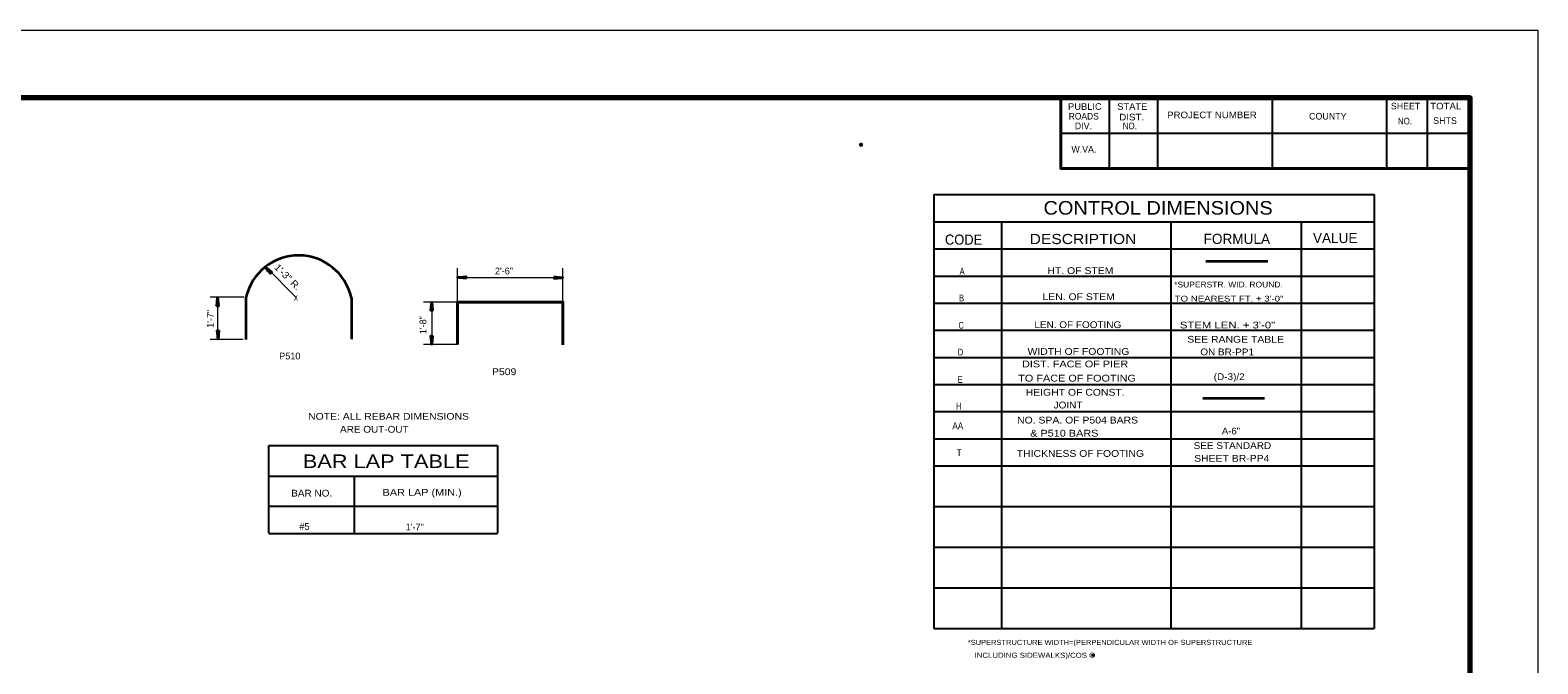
# Model space of a CAD drawing. Extents: x 3.64 to 6.84, y -0.8 to 1.19.
# Drawn here: x 4.986 to 6.841, y 0.413 to 1.192 of the extents above; entities that cross this region are included whole.
import ezdxf
from ezdxf.enums import TextEntityAlignment as Align

# ---------------------------------------------------------------- set-up
doc = ezdxf.new("R2010")
doc.units = 0
doc.header["$LTSCALE"] = 0.0033
doc.header["$PDMODE"] = 32
doc.header["$PDSIZE"] = 0.00165
doc.layers.add('1', color=7, linetype='Continuous', lineweight=40)

msp = doc.modelspace()

# ---------------------------------------------------------------- linework, layer by layer
at = {"layer": '1', "lineweight": 13}
for p, q in [((3.644833, 1.192083), (6.84125, 1.192083)), ((6.8415, 1.191917), (6.8415, -0.7945)), ((5.313417, 0.86375), (5.276333, 0.900833)), ((5.512167, 0.85775), (5.512167, 0.899417)), ((5.641833, 0.85775), (5.641833, 0.899417)), ((5.512667, 0.887833), (5.64025, 0.887833)), ((5.249333, 0.86375), (5.207667, 0.86375)), ((5.217083, 0.864083), (5.217083, 0.812583)), ((5.512167, 0.85775), (5.4705, 0.85775)), ((5.480417, 0.85775), (5.480417, 0.80625)), ((5.248333, 0.81175), (5.208, 0.81175)), ((5.512167, 0.8055), (5.4705, 0.8055))]:
    msp.add_line(p, q, dxfattribs=at)
at = {"layer": '1', "lineweight": 25}
for p, q in [((6.314083, 1.10875), (6.314083, 1.022083)), ((6.373667, 1.10875), (6.373667, 1.022083)), ((6.5145, 1.10875), (6.5145, 1.022083)), ((6.655333, 1.10875), (6.655333, 1.022083)), ((6.705167, 1.10875), (6.705167, 1.022083)), ((6.2545, 1.065417), (6.75825, 1.065417)), ((6.098417, 0.989833), (6.098417, 0.456333)), ((6.098417, 0.989833), (6.640083, 0.989833)), ((6.640083, 0.989833), (6.640083, 0.456333)), ((6.098417, 0.956333), (6.640083, 0.956333)), ((6.18175, 0.956333), (6.18175, 0.456333)), ((6.390083, 0.956333), (6.390083, 0.456333)), ((6.550417, 0.956333), (6.550417, 0.456333)), ((6.098417, 0.923), (6.640083, 0.923)), ((6.098417, 0.889667), (6.640083, 0.889667)), ((6.098417, 0.856333), (6.640083, 0.856333)), ((6.098417, 0.823), (6.640083, 0.823)), ((6.098417, 0.789667), (6.640083, 0.789667)), ((6.098417, 0.756333), (6.640083, 0.756333)), ((6.098417, 0.723), (6.640083, 0.723)), ((6.098417, 0.689667), (6.640083, 0.689667)), ((5.28, 0.68125), (5.561417, 0.68125)), ((5.28, 0.573417), (5.28, 0.68125)), ((5.561417, 0.68125), (5.561417, 0.573417)), ((6.098417, 0.656333), (6.640083, 0.656333)), ((5.28, 0.6435), (5.561417, 0.6435)), ((5.3855, 0.573417), (5.3855, 0.6435)), ((5.28, 0.606583), (5.561417, 0.606583)), ((6.098417, 0.606333), (6.640083, 0.606333)), ((5.28, 0.573083), (5.561417, 0.573083)), ((6.098417, 0.556333), (6.640083, 0.556333)), ((6.098417, 0.506333), (6.640083, 0.506333)), ((6.098417, 0.456333), (6.640083, 0.456333))]:
    msp.add_line(p, q, dxfattribs=at)
at = {"layer": '1', "lineweight": 35}
for p, q in [((5.283083, 0.89325), (5.275583, 0.90075)), ((5.282333, 0.892833), (5.277333, 0.899083)), ((5.282167, 0.892833), (5.277333, 0.899)), ((5.282167, 0.892833), (5.277333, 0.899)), ((5.28225, 0.892917), (5.277333, 0.899)), ((5.282333, 0.892833), (5.277583, 0.899167)), ((5.2835, 0.894083), (5.27775, 0.89875)), ((5.283417, 0.893917), (5.27775, 0.898583)), ((5.283583, 0.894167), (5.277833, 0.89875)), ((5.283667, 0.894333), (5.277917, 0.898917)), ((5.282583, 0.893833), (5.279167, 0.897083)), ((6.433083, 0.907917), (6.509083, 0.907917)), ((5.52275, 0.887833), (5.512167, 0.887833)), ((5.5225, 0.887), (5.514667, 0.888)), ((5.5225, 0.887), (5.514667, 0.887833)), ((5.5225, 0.886833), (5.514667, 0.88775)), ((5.5225, 0.886833), (5.514667, 0.88775)), ((5.5225, 0.886917), (5.514667, 0.88775)), ((5.5225, 0.888917), (5.515167, 0.888083)), ((5.5225, 0.88875), (5.515167, 0.888)), ((5.5225, 0.888667), (5.515167, 0.887833)), ((5.522583, 0.8885), (5.51525, 0.88775)), ((5.63125, 0.887833), (5.641833, 0.887833)), ((5.631417, 0.887167), (5.63875, 0.887917)), ((5.6315, 0.888833), (5.639333, 0.887917)), ((5.6315, 0.888833), (5.639333, 0.887917)), ((5.6315, 0.88875), (5.639333, 0.887917)), ((5.6315, 0.888667), (5.639333, 0.887833)), ((5.6315, 0.888667), (5.639333, 0.887667)), ((5.6315, 0.887), (5.638833, 0.887833)), ((5.6315, 0.886917), (5.638833, 0.887667)), ((5.6315, 0.88675), (5.638833, 0.887583)), ((5.216, 0.852833), (5.216917, 0.860667)), ((5.216, 0.852833), (5.216917, 0.860667)), ((5.216083, 0.852833), (5.216917, 0.860667)), ((5.216167, 0.852833), (5.217, 0.860667)), ((5.216167, 0.852833), (5.217167, 0.860667)), ((5.217667, 0.85275), (5.216917, 0.860083)), ((5.217, 0.852583), (5.217, 0.863167)), ((5.217833, 0.852833), (5.217, 0.860167)), ((5.217917, 0.852833), (5.217167, 0.860167)), ((5.218083, 0.852833), (5.21725, 0.860167)), ((5.251917, 0.863167), (5.251917, 0.811667)), ((5.381583, 0.862833), (5.381583, 0.812)), ((5.479417, 0.847417), (5.480333, 0.85525)), ((5.479417, 0.847417), (5.480333, 0.85525)), ((5.4795, 0.847417), (5.480333, 0.85525)), ((5.479583, 0.847417), (5.480417, 0.85525)), ((5.479583, 0.847417), (5.480583, 0.85525)), ((5.481083, 0.847333), (5.480333, 0.854667)), ((5.480417, 0.847167), (5.480417, 0.85775)), ((5.48125, 0.847417), (5.480417, 0.85475)), ((5.481333, 0.847417), (5.480583, 0.85475)), ((5.4815, 0.847417), (5.480667, 0.85475)), ((5.2165, 0.8225), (5.217333, 0.815167)), ((5.216667, 0.8225), (5.217417, 0.815167)), ((5.21675, 0.8225), (5.217583, 0.815167)), ((5.216917, 0.822583), (5.217667, 0.81525)), ((5.218417, 0.8225), (5.217417, 0.814667)), ((5.217583, 0.82275), (5.217583, 0.812167)), ((5.218417, 0.8225), (5.217583, 0.814667)), ((5.218583, 0.8225), (5.217667, 0.814667)), ((5.218583, 0.8225), (5.217667, 0.814667)), ((5.2185, 0.8225), (5.217667, 0.814667)), ((5.479333, 0.815917), (5.480167, 0.808583)), ((5.4795, 0.815917), (5.48025, 0.808583)), ((5.479583, 0.815917), (5.480417, 0.808583)), ((5.47975, 0.816), (5.4805, 0.808667)), ((5.48125, 0.815917), (5.48025, 0.808083)), ((5.480417, 0.816167), (5.480417, 0.805583)), ((5.48125, 0.815917), (5.480417, 0.808083)), ((5.481417, 0.815917), (5.4805, 0.808083)), ((5.481417, 0.815917), (5.4805, 0.808083)), ((5.481333, 0.815917), (5.4805, 0.808083)), ((6.429333, 0.739333), (6.505333, 0.739333)), ((6.2925, 0.423417), (6.296583, 0.423417))]:
    msp.add_line(p, q, dxfattribs=at)
at = {"layer": '1', "lineweight": 70}
msp.add_lwpolyline([(6.75825, -0.711333), (6.75825, 1.10875), (3.811583, 1.10875), (3.811583, -0.711333)], dxfattribs=at)
at = {"layer": '1'}
for points in [[(6.2545, 1.10875), (6.2545, 1.022083), (6.75825, 1.022083)], [(5.512167, 0.8055), (5.512167, 0.85775), (5.641833, 0.85775), (5.641833, 0.805167)]]:
    msp.add_lwpolyline(points, dxfattribs=at)
at = {"layer": '1', "lineweight": 35}
for points in [[(5.282417, 0.892583), (5.275583, 0.90075), (5.283917, 0.894083), (5.282667, 0.893667)], [(5.52275, 0.88675), (5.512167, 0.887833), (5.52275, 0.889), (5.522167, 0.887833)], [(5.522, 0.88775), (5.517333, 0.887667), (5.517333, 0.88775), (5.51825, 0.88775), (5.522, 0.887667), (5.519, 0.887583), (5.522167, 0.8875), (5.519917, 0.887417), (5.522167, 0.887333), (5.518667, 0.887583), (5.514, 0.88775), (5.514917, 0.888), (5.513667, 0.888), (5.522, 0.888), (5.519583, 0.888167), (5.522167, 0.888167), (5.516833, 0.88775), (5.522167, 0.888417)], [(5.63125, 0.888917), (5.641833, 0.887833), (5.63125, 0.886667), (5.631833, 0.887833)], [(5.632, 0.887917), (5.636667, 0.888), (5.636667, 0.887917), (5.63575, 0.887917), (5.632, 0.888), (5.635, 0.888083), (5.631833, 0.888167), (5.634083, 0.88825), (5.631833, 0.888333), (5.635333, 0.888083), (5.64, 0.887917), (5.639083, 0.887667), (5.640333, 0.887667), (5.632, 0.887667), (5.634417, 0.8875), (5.631833, 0.8875), (5.637167, 0.887917), (5.631833, 0.88725)], [(5.215917, 0.852583), (5.217, 0.863167), (5.218167, 0.852583), (5.217, 0.853167)], [(5.216917, 0.853333), (5.216833, 0.858), (5.216917, 0.858), (5.216917, 0.857083), (5.216833, 0.853333), (5.21675, 0.856333), (5.216667, 0.853167), (5.216583, 0.855417), (5.2165, 0.853167), (5.21675, 0.856667), (5.216917, 0.861333), (5.217167, 0.860417), (5.217167, 0.861667), (5.217167, 0.853333), (5.217333, 0.85575), (5.217333, 0.853167), (5.216917, 0.8585), (5.217583, 0.853167)], [(5.479333, 0.847167), (5.480417, 0.85775), (5.481583, 0.847167), (5.480417, 0.84775)], [(5.480333, 0.847917), (5.48025, 0.852583), (5.480333, 0.852583), (5.480333, 0.851667), (5.48025, 0.847917), (5.480167, 0.850917), (5.480083, 0.84775), (5.48, 0.85), (5.479917, 0.84775), (5.480167, 0.85125), (5.480333, 0.855917), (5.480583, 0.855), (5.480583, 0.85625), (5.480583, 0.847917), (5.48075, 0.850333), (5.48075, 0.84775), (5.480333, 0.853083), (5.481, 0.84775)], [(5.218667, 0.82275), (5.217583, 0.812167), (5.216417, 0.82275), (5.217583, 0.822167)], [(5.217667, 0.822), (5.21775, 0.817333), (5.217667, 0.817333), (5.217667, 0.81825), (5.21775, 0.822), (5.217833, 0.819), (5.217917, 0.822167), (5.218, 0.819917), (5.218083, 0.822167), (5.217833, 0.818667), (5.217667, 0.814), (5.217417, 0.814917), (5.217417, 0.813667), (5.217417, 0.822), (5.21725, 0.819583), (5.21725, 0.822167), (5.217667, 0.816833), (5.217, 0.822167)], [(5.4815, 0.816167), (5.480417, 0.805583), (5.47925, 0.816167), (5.480417, 0.815583)], [(5.4805, 0.815417), (5.480583, 0.81075), (5.4805, 0.81075), (5.4805, 0.811667), (5.480583, 0.815417), (5.480667, 0.812417), (5.48075, 0.815583), (5.480833, 0.813333), (5.480917, 0.815583), (5.480667, 0.812083), (5.4805, 0.807417), (5.48025, 0.808333), (5.48025, 0.807083), (5.48025, 0.815417), (5.480083, 0.813), (5.480083, 0.815583), (5.4805, 0.81025), (5.479833, 0.815583)]]:
    msp.add_lwpolyline(points, close=True, dxfattribs=at)
for points in [[(5.279167, 0.897083), (5.279917, 0.8965), (5.282417, 0.89375), (5.28025, 0.89575), (5.282417, 0.8935), (5.28075, 0.895083), (5.282417, 0.893417), (5.28, 0.896083), (5.276917, 0.8995), (5.277667, 0.898917), (5.27675, 0.899917), (5.282667, 0.893917), (5.281167, 0.895833), (5.283, 0.894), (5.278917, 0.8975), (5.283083, 0.894083), (5.282583, 0.893833), (5.28225, 0.892917), (5.28225, 0.89325), (5.282417, 0.893667), (5.282167, 0.893833), (5.282, 0.8935), (5.282667, 0.893917), (5.283167, 0.894083), (5.283583, 0.89425)], [(5.522, 0.88775), (5.522417, 0.887), (5.522167, 0.88725), (5.522, 0.887583), (5.52175, 0.8875), (5.521917, 0.887167), (5.522083, 0.887917), (5.52225, 0.888417), (5.5225, 0.888833)], [(5.632, 0.887917), (5.631583, 0.888667), (5.631833, 0.888417), (5.632, 0.888083), (5.63225, 0.888167), (5.632083, 0.8885), (5.631917, 0.88775), (5.63175, 0.88725), (5.6315, 0.886833)], [(5.216917, 0.853333), (5.216167, 0.852917), (5.216417, 0.853167), (5.21675, 0.853333), (5.216667, 0.853583), (5.216333, 0.853417), (5.217083, 0.85325), (5.217583, 0.853083), (5.218, 0.852833)], [(5.480333, 0.847917), (5.479583, 0.8475), (5.479833, 0.84775), (5.480167, 0.847917), (5.480083, 0.848167), (5.47975, 0.848), (5.4805, 0.847833), (5.481, 0.847667), (5.481417, 0.847417)], [(5.217667, 0.822), (5.218417, 0.822417), (5.218167, 0.822167), (5.217833, 0.822), (5.217917, 0.82175), (5.21825, 0.821917), (5.2175, 0.822083), (5.217, 0.82225), (5.216583, 0.8225)], [(5.4805, 0.815417), (5.48125, 0.815833), (5.481, 0.815583), (5.480667, 0.815417), (5.48075, 0.815167), (5.481083, 0.815333), (5.480333, 0.8155), (5.479833, 0.815667), (5.479417, 0.815917)]]:
    msp.add_lwpolyline(points, dxfattribs=at)
msp.add_arc((5.316713, 0.848654), 0.066402, 12.33016, 167.37526, dxfattribs=at)
at = {"layer": '1'}
for p in [(6.00875, 1.05125), (5.279167, 0.897083)]:
    msp.add_point(p, dxfattribs=at)

# ---------------------------------------------------------------- texts
for s, height, width, p in [('PUBLIC', 0.008167, 1.05, (6.284167, 1.094083)), ('STATE', 0.008167, 1.05, (6.3425, 1.094083)), ('TOTAL', 0.008084, 1.1, (6.728167, 1.094667)), ('ROADS', 0.008167, 0.95, (6.28275, 1.082167)), ('DIST.', 0.008167, 1.1, (6.341792, 1.081083)), ('NO.', 0.008167, 0.9, (6.339458, 1.07025)), ('PROJECT NUMBER', 0.008084, 1.1, (6.440458, 1.083833)), ('NO.', 0.008084, 0.9, (6.677958, 1.07625)), ('x', 0.008334, 0.85, (5.313417, 0.859583)), ('HEIGHT OF CONST.', 0.008334, 1.15, (6.272208, 0.742583)), ('H', 0.008334, 0.65, (6.128792, 0.7255)), ('JOINT', 0.008334, 1.1, (6.263417, 0.726833)), ('AA', 0.008334, 0.9, (6.127833, 0.701333)), ('A-6"', 0.008334, 1.05, (6.463917, 0.694917)), ('T', 0.008334, 0.8, (6.129458, 0.668333)), ('THICKNESS OF FOOTING', 0.008334, 1.15, (6.278625, 0.667333)), ('SEE STANDARD', 0.008334, 1.1, (6.465667, 0.677)), ('SHEET BR-PP4', 0.008334, 1.15, (6.464917, 0.661333))]:
    msp.add_text(s, height=height, dxfattribs=dict(at, width=width)).set_placement(p, align=Align.CENTER)
for s, height, p in [('SHEET', 0.008084, (6.67875, 1.094667)), ('DIV.', 0.008167, (6.282333, 1.07025)), ('COUNTY', 0.008167, (6.583083, 1.082167)), ('SHTS', 0.008167, (6.727333, 1.07675)), ('W.VA.', 0.008084, (6.282917, 1.041583))]:
    msp.add_text(s, height=height, dxfattribs=at).set_placement(p, align=Align.CENTER)
for s, height, width, p in [('CONTROL DIMENSIONS', 0.01667, 1.1, (6.23325, 0.96525)), ('CODE', 0.0125, 0.95, (6.112, 0.92825)), ('DESCRIPTION ', 0.0125, 1.15, (6.216167, 0.929)), ('A', 0.008334, 0.75, (6.130083, 0.891583)), ('HT. OF STEM', 0.008334, 1.15, (6.238083, 0.89225)), ('*SUPERSTR. WID. ROUND. ', 0.007083, 1.1, (6.394, 0.875667)), ('B', 0.008334, 0.75, (6.129417, 0.858583)), ('LEN. OF STEM', 0.008334, 1.15, (6.231917, 0.860083)), ('TO NEAREST FT. + 3\'-0"', 0.007083, 1.25, (6.39475, 0.858333)), ('C', 0.008334, 0.65, (6.128667, 0.824917)), ('LEN. OF FOOTING', 0.008334, 1.1, (6.222, 0.825667)), ('STEM LEN. + 3\'-0"', 0.008334, 1.25, (6.401083, 0.82525)), ('D', 0.008334, 0.65, (6.127833, 0.792)), ('WIDTH OF FOOTING', 0.008334, 1.15, (6.213583, 0.79275)), ('SEE RANGE TABLE', 0.008334, 1.15, (6.410167, 0.80775)), ('ON BR-PP1', 0.008334, 1.1, (6.426167, 0.79225)), ('DIST. FACE OF PIER', 0.008334, 1.2, (6.20675, 0.777417)), ('P509', 0.008334, 1.15, (5.554667, 0.767833)), ('E', 0.008334, 0.75, (6.127833, 0.758333)), ('TO FACE OF FOOTING', 0.008334, 1.2, (6.202083, 0.759917)), ('(D-3)/2', 0.008334, 1.1, (6.442667, 0.76175)), ('NOTE: ALL REBAR DIMENSIONS', 0.008334, 1.15, (5.328333, 0.713)), ('ARE OUT-OUT', 0.008334, 1.1, (5.367667, 0.697083)), ('NO. SPA. OF P504 BARS', 0.008334, 1.15, (6.20075, 0.708333)), ('& P510 BARS', 0.008334, 1.2, (6.216833, 0.69225)), ('BAR LAP TABLE', 0.01667, 1.2, (5.321833, 0.653583)), ('BAR NO.', 0.008334, 1.1, (5.307583, 0.6185)), ('BAR LAP (MIN.)', 0.008334, 1.2, (5.42, 0.6195)), ('*SUPERSTRUCTURE WIDTH=(PERPENDICULAR WIDTH OF SUPERSTRUCTURE', 0.00625, 1.1, (6.140083, 0.436)), ('INCLUDING SIDEWALKS)/COS O', 0.00625, 1.15, (6.148417, 0.420167))]:
    msp.add_text(s, height=height, dxfattribs=dict(at, width=width)).set_placement(p)
for s, height, p in [('FORMULA', 0.0125, (6.43025, 0.929167)), ('VALUE', 0.0125, (6.56475, 0.93025)), ('2\'-6"', 0.008334, (5.55825, 0.89175)), ('P510', 0.008334, (5.292833, 0.787167)), ('#5', 0.008334, (5.317667, 0.5775)), ('1\'-7"', 0.008334, (5.448417, 0.576833))]:
    msp.add_text(s, height=height, dxfattribs=at).set_placement(p)
at = {"layer": '1', "width": 1.1}
msp.add_text('1\'-3" R.', height=0.008333, rotation=315, dxfattribs=at).set_placement((5.286083, 0.899667))
at = {"layer": '1'}
for s, p in [('1\'-7"', (5.212167, 0.826)), ('1\'-8"', (5.473833, 0.81825))]:
    msp.add_text(s, height=0.008334, rotation=90, dxfattribs=at).set_placement(p)

doc.saveas('drawing.dxf')
